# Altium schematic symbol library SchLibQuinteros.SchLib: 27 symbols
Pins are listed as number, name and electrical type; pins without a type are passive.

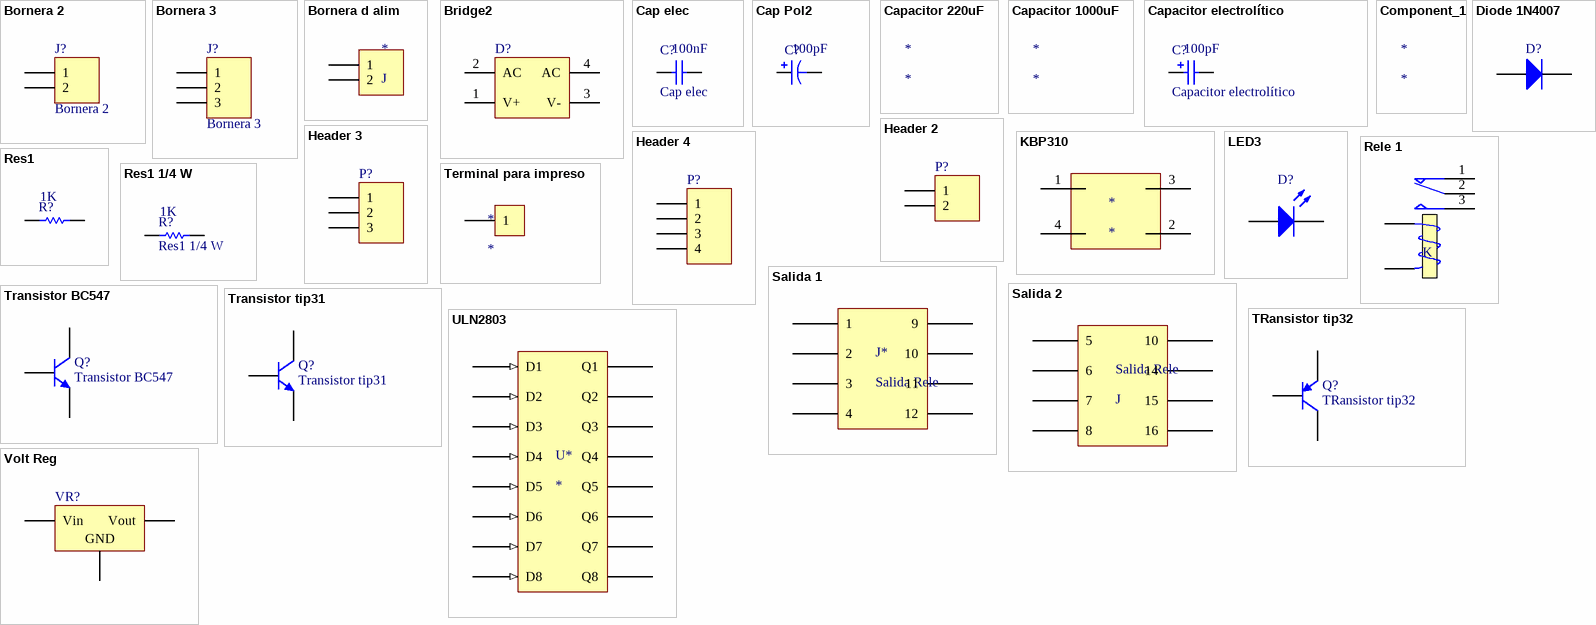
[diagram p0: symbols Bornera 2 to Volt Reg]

## Bornera 2
designator J?
footprint ED130-2P (Connector; Header; 2 Position)
signal-integrity model Connector
pins: 1, 2

## Bornera 3
designator J?
Bornera, 3 Pin
signal-integrity model Connector
footprint ED130-3P (Connector; Header; 2 Position)
pins: 1, 2, 3

## Bornera d alim
designator *, comment J
footprint bornera de alim
pins: 1, 2

## Bridge2
designator D?
Diode Bridge
simulation model BRIDGE (Spice Subcircuit)
footprint KBP310 (Axial Device, Thru-Hole; 2 Leads; 0.4 in Pin Spacing)
pins: 1 V+, 2 AC, 3 V-, 4 AC

## Cap elec
designator C?  value 100nF
Polarized Capacitor (Radial)
simulation model CAP (Capacitor)
signal-integrity model Cap Pol
footprint Cap Elec 100nF (Polarized Capacitor (Radial); 2 Leads)
pins: 1, 2
1 alternate drawing of the same symbol

## Cap Pol2
designator C?  value 100pF
Polarized Capacitor (Axial)
footprint POLAR0.8 (Polarized Capacitor; 2 Leads)
simulation model CAP (Capacitor)
signal-integrity model Cap Pol
pins: 1, 2
1 alternate drawing of the same symbol

## Capacitor 220uF
designator *

## Capacitor 1000uF
designator *

## Capacitor electrolítico
designator C?  value 100pF
Polarized Capacitor (Radial)
footprint RB7.6-15 (Polarized Capacitor (Radial); 2 Leads)
simulation model CAP (Capacitor)
signal-integrity model Cap Pol
pins: 1, 2
1 alternate drawing of the same symbol

## Component_1
designator *

## Diode 1N4007
designator D?
1 Amp General Purpose Rectifier
footprint DO-41 (Diode, Axial; Body 5.2 x 2.7 mm (LxDia. max), Lead Dia. 0.86 mm (max))
simulation model 1N4007 (DIODE)
signal-integrity model 1N4007
pins: 1 A, 2 K

## Header 2
designator P?
Header, 2-Pin
footprint HDR1X2 (Connector; Header; 2 Position)
signal-integrity model Connector
pins: 1, 2

## Header 3
designator P?
Header, 3-Pin
footprint HDR1X3 (Connector; Header; 3 Position)
signal-integrity model Connector
pins: 1, 2, 3

## Header 4
designator P?
Header, 4-Pin
footprint HDR1X4 (Connector; Header; 4 Position)
signal-integrity model Connector
pins: 1, 2, 3, 4

## KBP310
designator *
footprint KBP310 (Axial Device, Thru-Hole; 2 Leads; 0.4 in Pin Spacing)
pins: 1 4, 2 6, 3 5, 4 7

## LED3
designator D?
Typical BLUE SiC LED
simulation model LED3 (Diode)
signal-integrity model LED
footprint LED (LED; 2 Leads)
pins: 1 A, 2 K

## Rele 1
designator *, comment K
footprint Rele
pins: 1 NC, 2 COM, 3 NO, 4, 5

## Res1
designator R?  value 1K
Resistor
simulation model RESISTOR (Resistor)
signal-integrity model Res
footprint AXIAL-0.4 (Axial Device, Thru-Hole; 2 Leads; 0.4 in Pin Spacing)
pins: 1, 2

## Res1 1/4 W
designator R?  value 1K
Resistor
simulation model RESISTOR (Resistor)
signal-integrity model Res
footprint AXIAL-0.4 - 1/4 W (Axial Device, Thru-Hole; 2 Leads; 0.4 in Pin Spacing)
pins: 1, 2

## Salida 1
designator J*, comment Salida Rele
footprint Conector de Salida
pins: 1, 2 9, 3 2, 4 10, 5 3, 6 11, 7 4, 8 12

## Salida 2
designator Salida Rele, comment J
footprint Conector de salida 2
pins: 9 5, 10, 11 6, 12 14, 13 7, 14 15, 15 8, 16

## Terminal para impreso
designator *
pins: 1

## Transistor BC547
designator Q?
NPN General Purpose Amplifier
footprint SOT-92-CBW (TO, Flat Index; 3 In-Line, Axial Leads; Body Dia. 4.5mm; Leads 0.51 x 0.48 mm (max))
simulation model 2N3904 (NPN)
signal-integrity model 2N3904
pins: 1 C, 2 B, 3 E

## Transistor tip31
designator Q?
NPN General Purpose Amplifier
footprint TO-220AB (TO, Thru-Hole, Vertical, Heatsink Mounted; 3 In-Line Leads; Pitch 2.54 mm)
simulation model 2N3904 (NPN)
signal-integrity model 2N3904
pins: 1 B, 2 C, 3 E

## TRansistor tip32
designator Q?
PNP General Purpose Amplifier
footprint TO-220AB (TO, Thru-Hole, Vertical, Heatsink Mounted; 3 In-Line Leads; Pitch 2.54 mm)
simulation model 2N3906 (PNP)
signal-integrity model 2N3906
pins: 1 B, 2 C, 3 E

## ULN2803
designator U*
footprint ULN2803
pins: 1 D1 (in), 2 D2 (in), 3 D3 (in), 4 D4 (in), 5 D5 (in), 6 D6 (in), 7 D7 (in), 8 D8 (in), 11 Q1, 12 Q2, 13 Q3, 14 Q4, 15 Q5, 16 Q6, 17 Q7, 18 Q8

## Volt Reg
designator VR?
Voltage Regulator
footprint VRM (Connector; Header; 3 Position)
pins: 1 Vin, 2 GND, 3 Vout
